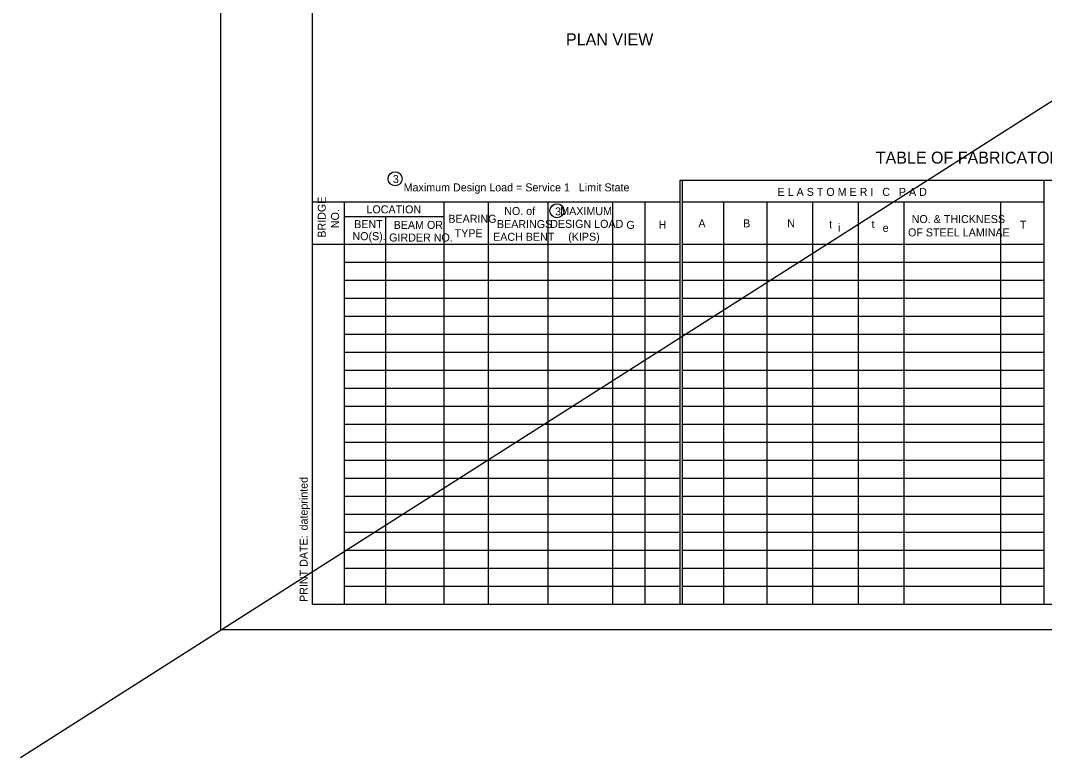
# Model space of a CAD drawing. Extents: x 113 to 232, y -103 to -27.
# Drawn here: x 113.16 to 123.82, y -61.95 to -54.27 of the extents above; entities that cross this region are included whole.
import ezdxf

# ---------------------------------------------------------------- set-up
doc = ezdxf.new("R2010")
doc.units = 0
for name, color, linetype in [('1', 7, 'Continuous'), ('B_Border', 7, 'Continuous'), ('B_No_Plot', 7, 'Continuous')]:
    doc.layers.add(name, color=color, linetype=linetype)

msp = doc.modelspace()

# ---------------------------------------------------------------- linework, layer by layer
at = {"layer": '1'}
for p, q in [((113.16, -61.947), (139.431, -45.215)), ((120.023, -55.936), (120.023, -56.164)), ((124.32, -55.936), (120.023, -55.936)), ((120.048, -55.936), (120.048, -56.164)), ((123.812, -55.936), (123.812, -56.164)), ((117.565, -56.164), (116.199, -56.164)), ((116.528, -56.164), (116.528, -60.354)), ((117.565, -56.164), (117.565, -60.354)), ((117.565, -56.164), (117.565, -60.354)), ((120.023, -56.164), (117.565, -56.164)), ((118.028, -56.164), (118.028, -60.354)), ((118.649, -56.164), (118.649, -60.354)), ((119.321, -56.164), (119.321, -60.354)), ((119.66, -56.164), (119.66, -60.354)), ((120.023, -56.164), (120.023, -60.354)), ((122.379, -56.164), (120.048, -56.164)), ((120.048, -56.164), (120.048, -60.354)), ((120.478, -56.164), (120.478, -60.354)), ((120.929, -56.164), (120.929, -60.354)), ((120.929, -56.164), (120.929, -60.354)), ((121.404, -56.164), (121.404, -60.354)), ((121.879, -56.164), (121.879, -60.354)), ((122.354, -56.164), (122.354, -60.354)), ((123.812, -56.164), (122.372, -56.164)), ((123.362, -56.164), (123.362, -60.354)), ((123.812, -56.164), (123.812, -60.354)), ((117.565, -56.315), (116.528, -56.315)), ((116.958, -56.315), (116.958, -60.358)), ((116.509, -56.604), (116.199, -56.604)), ((117.565, -56.604), (116.509, -56.604)), ((120.023, -56.604), (117.565, -56.604)), ((123.354, -56.604), (120.048, -56.604)), ((123.812, -56.604), (123.354, -56.604)), ((117.565, -56.791), (116.528, -56.791)), ((120.023, -56.791), (117.565, -56.791)), ((123.354, -56.791), (120.048, -56.791)), ((123.812, -56.791), (123.354, -56.791)), ((117.565, -56.979), (116.528, -56.979)), ((120.023, -56.979), (117.565, -56.979)), ((123.354, -56.979), (120.048, -56.979)), ((123.812, -56.979), (123.354, -56.979)), ((117.565, -57.166), (116.528, -57.166)), ((120.023, -57.166), (117.565, -57.166)), ((123.354, -57.166), (120.048, -57.166)), ((123.812, -57.166), (123.354, -57.166)), ((117.565, -57.354), (116.528, -57.354)), ((120.023, -57.354), (117.565, -57.354)), ((123.354, -57.354), (120.048, -57.354)), ((123.812, -57.354), (123.354, -57.354)), ((117.565, -57.541), (116.528, -57.541)), ((120.023, -57.541), (117.565, -57.541)), ((123.354, -57.541), (120.048, -57.541)), ((123.812, -57.541), (123.354, -57.541)), ((117.565, -57.729), (116.528, -57.729)), ((120.023, -57.729), (117.565, -57.729)), ((123.354, -57.729), (120.048, -57.729)), ((123.812, -57.729), (123.354, -57.729)), ((117.565, -57.916), (116.528, -57.916)), ((120.023, -57.916), (117.565, -57.916)), ((123.354, -57.916), (120.048, -57.916)), ((123.812, -57.916), (123.354, -57.916)), ((117.565, -58.104), (116.528, -58.104)), ((120.023, -58.104), (117.565, -58.104)), ((123.354, -58.104), (120.048, -58.104)), ((123.812, -58.104), (123.354, -58.104)), ((117.565, -58.291), (116.528, -58.291)), ((120.023, -58.291), (117.565, -58.291)), ((123.354, -58.291), (120.048, -58.291)), ((123.812, -58.291), (123.354, -58.291)), ((117.565, -58.479), (116.528, -58.479)), ((120.023, -58.479), (117.565, -58.479)), ((123.354, -58.479), (120.048, -58.479)), ((123.812, -58.479), (123.354, -58.479)), ((117.565, -58.666), (116.528, -58.666)), ((120.023, -58.666), (117.565, -58.666)), ((123.354, -58.666), (120.048, -58.666)), ((123.812, -58.666), (123.354, -58.666)), ((117.565, -58.854), (116.528, -58.854)), ((120.023, -58.854), (117.565, -58.854)), ((123.354, -58.854), (120.048, -58.854)), ((123.812, -58.854), (123.354, -58.854)), ((117.565, -59.041), (116.528, -59.041)), ((120.023, -59.041), (117.565, -59.041)), ((123.354, -59.041), (120.048, -59.041)), ((123.812, -59.041), (123.354, -59.041)), ((117.565, -59.229), (116.528, -59.229)), ((120.023, -59.229), (117.565, -59.229)), ((123.354, -59.229), (120.048, -59.229)), ((123.812, -59.229), (123.354, -59.229)), ((117.565, -59.416), (116.528, -59.416)), ((120.023, -59.416), (117.565, -59.416)), ((123.354, -59.416), (120.048, -59.416)), ((123.812, -59.416), (123.354, -59.416)), ((117.565, -59.604), (116.528, -59.604)), ((120.023, -59.604), (117.565, -59.604)), ((123.354, -59.604), (120.048, -59.604)), ((123.812, -59.604), (123.354, -59.604)), ((117.565, -59.791), (116.528, -59.791)), ((120.023, -59.791), (117.565, -59.791)), ((123.354, -59.791), (120.048, -59.791)), ((123.812, -59.791), (123.354, -59.791)), ((117.565, -59.979), (116.528, -59.979)), ((120.023, -59.979), (117.565, -59.979)), ((123.354, -59.979), (120.048, -59.979)), ((123.812, -59.979), (123.354, -59.979)), ((117.565, -60.166), (116.528, -60.166)), ((120.023, -60.166), (117.565, -60.166)), ((123.354, -60.166), (120.048, -60.166)), ((123.812, -60.166), (123.354, -60.166)), ((116.509, -60.354), (116.199, -60.354)), ((120.023, -60.354), (119.958, -60.354))]:
    msp.add_line(p, q, dxfattribs=at)
for centre in [(117.059, -55.92), (118.744, -56.253)]:
    msp.add_circle(centre, 0.0733, dxfattribs=at)
at = {"layer": 'B_Border'}
for p, q in [((116.198, -60.354), (116.198, -46.658)), ((116.199, -60.354), (116.199, -46.658)), ((137.275, -60.354), (116.198, -60.354))]:
    msp.add_line(p, q, dxfattribs=at)
at = {"layer": 'B_No_Plot'}
msp.add_lwpolyline([(115.246, -46.394), (137.58, -46.394), (137.58, -60.618), (115.246, -60.618)], close=True, dxfattribs=at)

# ---------------------------------------------------------------- texts
at = {"layer": '1'}
for s, height, p in [('PLAN VIEW', 0.1248, (118.838, -54.53)), ('TABLE OF FABRICATOR VARIABLES', 0.12483, (122.062, -55.762)), ('3', 0.0833, (117.036, -55.964)), ('Maximum Design Load = Service 1   Limit State', 0.08333, (117.148, -56.051)), ('E L A S T O M E R I   C   P A D', 0.08333, (121.04, -56.098)), ('LOCATION', 0.0833, (116.761, -56.28)), ('NO. of ', 0.0833, (118.195, -56.297)), ('3', 0.0833, (118.724, -56.301)), ('  MAXIMUM', 0.0833, (118.716, -56.298)), ('BENT', 0.0833, (116.633, -56.434)), ('BEAM OR', 0.0833, (117.044, -56.442)), ('BEARING', 0.0833, (117.613, -56.378)), ('BEARINGS', 0.0833, (118.119, -56.433)), ('DESIGN LOAD', 0.08333, (118.673, -56.431)), ('G', 0.0833, (119.467, -56.442)), ('H', 0.0833, (119.802, -56.439)), ('A', 0.0833, (120.216, -56.426)), ('B', 0.0833, (120.682, -56.426)), ('N', 0.0833, (121.141, -56.426)), ('t', 0.0833, (121.577, -56.436)), ('i', 0.0833, (121.669, -56.47)), (' t ', 0.0833, (121.988, -56.433)), ('NO. & THICKNESS', 0.08333, (122.436, -56.381)), ('T', 0.0833, (123.562, -56.44)), ('NO(S).', 0.0833, (116.615, -56.559)), ('GIRDER NO.', 0.0833, (116.997, -56.573)), ('TYPE', 0.0833, (117.679, -56.529)), ('EACH BENT', 0.0833, (118.079, -56.566)), ('(KIPS)', 0.0833, (118.861, -56.565)), ('e', 0.0833, (122.134, -56.473)), ('OF STEEL LAMINAE', 0.08333, (122.398, -56.52))]:
    msp.add_text(s, height=height, dxfattribs=at).set_placement(p)
for s, p in [('BRIDGE', (116.337, -56.533)), ('NO.', (116.476, -56.434))]:
    msp.add_text(s, height=0.0833, rotation=90, dxfattribs=at).set_placement(p)
at = {"layer": 'B_Border'}
for s, p in [('dateprinted', (116.149, -59.582)), ('PRINT DATE:  ', (116.149, -60.327))]:
    msp.add_text(s, height=0.08333, rotation=90, dxfattribs=at).set_placement(p)

doc.saveas('drawing.dxf')
